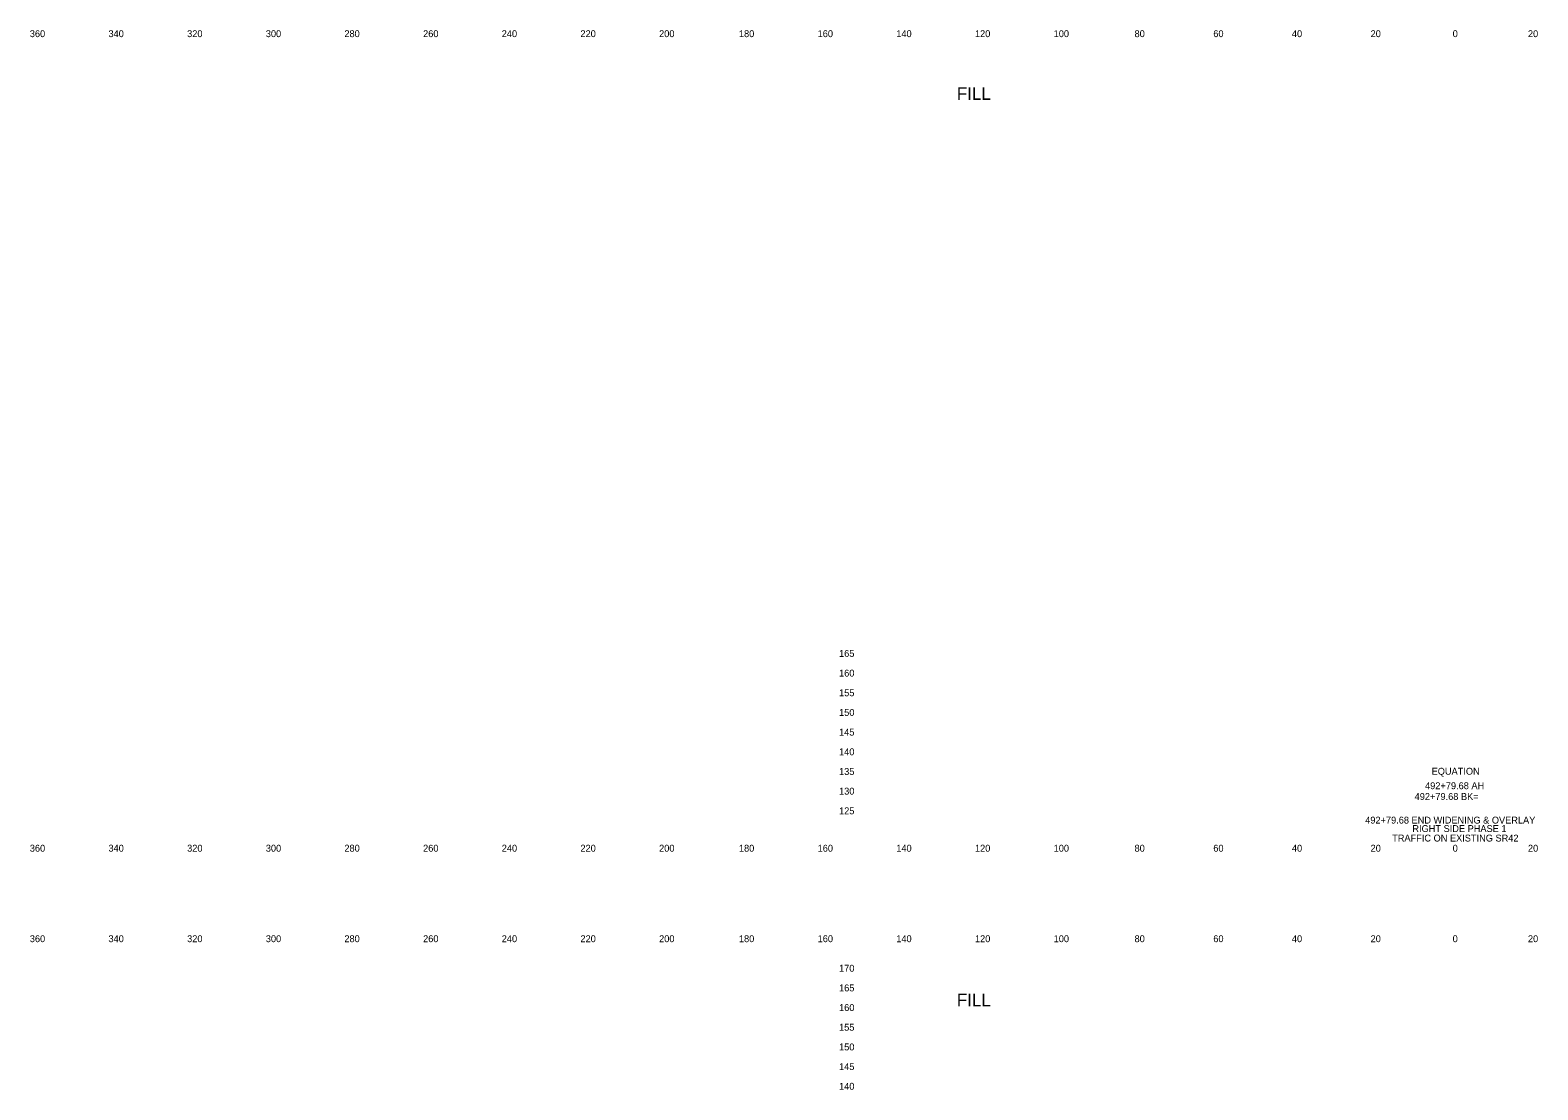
# Model space of a CAD drawing. Extents: x 21281 to 22024, y 6472 to 15198.
# Drawn here: x 21280.5 to 21663.8, y 14924.8 to 15194.1 of the extents above; entities that cross this region are included whole.
import ezdxf

# ---------------------------------------------------------------- set-up
doc = ezdxf.new("R2010")
doc.units = 0
for name, color, linetype in [('XS_SHEET_LABELS_ELEVATION', 7, 'Continuous'), ('XS_SHEET_LABELS_OFFSET', 7, 'Continuous'), ('XS_SHEET_LABELS_STATION', 7, 'Continuous')]:
    doc.layers.add(name, color=color, linetype=linetype)

msp = doc.modelspace()

# ---------------------------------------------------------------- texts
at = {"layer": 'XS_SHEET_LABELS_ELEVATION'}
for s, p in [('  165  ', (21484.84, 15034.84)), ('  160  ', (21484.84, 15029.84)), ('  155  ', (21484.84, 15024.84)), ('  150  ', (21484.84, 15019.84)), ('  145  ', (21484.84, 15014.84)), ('  140  ', (21484.84, 15009.84)), ('  135  ', (21484.84, 15004.84)), ('  130  ', (21484.84, 14999.84)), ('  125  ', (21484.84, 14994.84)), ('  170  ', (21484.84, 14954.84)), ('  165  ', (21484.84, 14949.84)), ('  160  ', (21484.84, 14944.84)), ('  155  ', (21484.84, 14939.84)), ('  150  ', (21484.84, 14934.84)), ('  145  ', (21484.84, 14929.84)), ('  140  ', (21484.84, 14924.84))]:
    msp.add_text(s, height=1.75, dxfattribs=at).set_placement(p)
at = {"layer": 'XS_SHEET_LABELS_OFFSET'}
for s, height, p in [('  360  ', 1.75, (21279.14, 15192.34)), ('  340  ', 1.75, (21299.13, 15192.34)), ('  320  ', 1.75, (21319.13, 15192.34)), ('  300  ', 1.75, (21339.13, 15192.34)), ('  280  ', 1.75, (21359.1, 15192.34)), ('  260  ', 1.75, (21379.11, 15192.34)), ('  240  ', 1.75, (21399.1, 15192.34)), ('  220  ', 1.75, (21419.1, 15192.34)), ('  200  ', 1.75, (21439.1, 15192.34)), ('  180  ', 1.75, (21459.39, 15192.34)), ('  160  ', 1.75, (21479.4, 15192.34)), ('  140  ', 1.75, (21499.39, 15192.34)), ('  120  ', 1.75, (21519.39, 15192.34)), ('  100  ', 1.75, (21539.39, 15192.34)), ('  80  ', 1.75, (21559.95, 15192.34)), ('  60  ', 1.75, (21579.97, 15192.34)), ('  40  ', 1.75, (21599.95, 15192.34)), ('  20  ', 1.75, (21619.95, 15192.34)), ('  0  ', 1.75, (21640.81, 15192.34)), ('  0  ', 1.75, (21640.81, 15192.34)), ('  20  ', 1.75, (21659.95, 15192.34)), ('FILL', 3.222, (21516.08, 15176.39)), ('  360  ', 1.75, (21279.14, 14985.34)), ('  340  ', 1.75, (21299.13, 14985.34)), ('  320  ', 1.75, (21319.13, 14985.34)), ('  300  ', 1.75, (21339.13, 14985.34)), ('  280  ', 1.75, (21359.1, 14985.34)), ('  260  ', 1.75, (21379.11, 14985.34)), ('  240  ', 1.75, (21399.1, 14985.34)), ('  220  ', 1.75, (21419.1, 14985.34)), ('  200  ', 1.75, (21439.1, 14985.34)), ('  180  ', 1.75, (21459.39, 14985.34)), ('  160  ', 1.75, (21479.4, 14985.34)), ('  140  ', 1.75, (21499.39, 14985.34)), ('  120  ', 1.75, (21519.39, 14985.34)), ('  100  ', 1.75, (21539.39, 14985.34)), ('  80  ', 1.75, (21559.95, 14985.34)), ('  60  ', 1.75, (21579.97, 14985.34)), ('  40  ', 1.75, (21599.95, 14985.34)), ('  20  ', 1.75, (21619.95, 14985.34)), ('  0  ', 1.75, (21640.81, 14985.34)), ('  0  ', 1.75, (21640.81, 14985.34)), ('  20  ', 1.75, (21659.95, 14985.34)), ('  360  ', 1.75, (21279.14, 14962.34)), ('  340  ', 1.75, (21299.13, 14962.34)), ('  320  ', 1.75, (21319.13, 14962.34)), ('  300  ', 1.75, (21339.13, 14962.34)), ('  280  ', 1.75, (21359.1, 14962.34)), ('  260  ', 1.75, (21379.11, 14962.34)), ('  240  ', 1.75, (21399.1, 14962.34)), ('  220  ', 1.75, (21419.1, 14962.34)), ('  200  ', 1.75, (21439.1, 14962.34)), ('  180  ', 1.75, (21459.39, 14962.34)), ('  160  ', 1.75, (21479.4, 14962.34)), ('  140  ', 1.75, (21499.39, 14962.34)), ('  120  ', 1.75, (21519.39, 14962.34)), ('  100  ', 1.75, (21539.39, 14962.34)), ('  80  ', 1.75, (21559.95, 14962.34)), ('  60  ', 1.75, (21579.97, 14962.34)), ('  40  ', 1.75, (21599.95, 14962.34)), ('  20  ', 1.75, (21619.95, 14962.34)), ('  0  ', 1.75, (21640.81, 14962.34)), ('  0  ', 1.75, (21640.81, 14962.34)), ('  20  ', 1.75, (21659.95, 14962.34)), ('FILL', 3.222, (21516.08, 14946.05))]:
    msp.add_text(s, height=height, dxfattribs=at).set_placement(p)
at = {"layer": 'XS_SHEET_LABELS_STATION'}
for s, p in [('EQUATION', (21636.76, 15004.9)), ('  492+79.68 BK= ', (21631.14, 14998.48)), ('492+79.68 AH', (21635.1, 15001.22)), (' 492+79.68 END WIDENING & OVERLAY', (21619.23, 14992.48)), ('TRAFFIC ON EXISTING SR42', (21626.73, 14987.92)), ('RIGHT SIDE PHASE 1', (21631.87, 14990.33))]:
    msp.add_text(s, height=1.75, dxfattribs=at).set_placement(p)

doc.saveas('drawing.dxf')
